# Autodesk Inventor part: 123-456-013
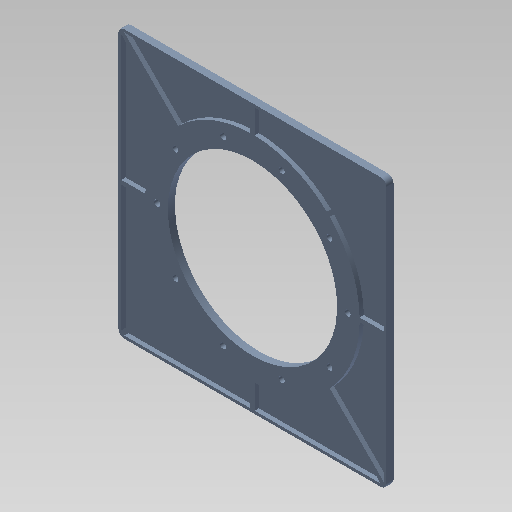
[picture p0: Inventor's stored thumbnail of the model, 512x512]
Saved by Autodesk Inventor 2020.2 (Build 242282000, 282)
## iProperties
Created: 2006-08
Part Number: 123-456-013
Document SubType Name: Modeling
Designer: F.Stasiak
Material: Staliwo
Description: Płyta
Density: 7.85 g/cm^3
Appearance: Stalowoniebieska - jasna
Mass: 74990.7 g
Surface Area: 15199.3 cm^2
Volume: 9552.95 cm^3
Manager: www.cadconsulting.pl
Company: Fabian Stasiak CAD Consulting
KODMAT: 14-2590
Author: F.Stasiak
Subject: Zbiór ćwiczeń. Autodesk Inventor 2020. Kurs podstawowy
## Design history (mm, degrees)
sketch "Szkic1"
  geometry: L1 (0, 475)-(950, 475); L2 (950, 475)-(950, -475); L3 (950, -475)-(0, -475); L4 (0, -475)-(0, 475); L5 (0, 0)-(950, 0); C1 r 300 at (475, 0); 1 further point
  constraints: 10 end point, 3 midpoint, 2 parallel, 1 centre point, 1 coincident, 1 horizontal, 1 perpendicular
  dimensions: "d0" = 950 distance of L3.end L1.start; "d1" = 950 distance of L2.end L3.end; "d2" = 600 diameter of C1
extrude "Wyciągnięcie proste1" new body sketch "Szkic1" distance "d3" = 25; taper "d4" = 0 deg
fillet "Zaokrąglenie1" dims "d8" = 20
feature "Skorupa1" dims "d9" = 80, "d10" = 10
sketch "Szkic2"
  geometry: L1 (455, -465)-(-455, -465) reference; L2 (465, 455)-(465, -455) reference; L3 (-455, 465)-(455, 465) reference; L4 (-465, -455)-(-465, 455) reference; L5 (-455, 455)-(455, -455); L6 (-455, -455)-(455, 455); L7 (-465, 0)-(465, 0); L8 (0, -465)-(0, 465); C1 r 380 at (0, 0) reference; C2 r 380 at (0, 0) reference; A1 r 10 centre (-455, -455) between (-465, -455) and (-455, -465) reference; A2 r 10 centre (455, -455) between (455, -465) and (465, -455) reference; A3 r 10 centre (455, 455) between (465, 455) and (455, 465) reference; A4 r 10 centre (-455, 455) between (-455, 465) and (-465, 455) reference
  constraints: 8 end point, 4 midpoint, 1 perpendicular
feature "Żebro1" sketch "Szkic2" dims "d11" = 15, "d12" = 1, "d13" = 0
sketch "Szkic3"
  geometry: 10 further points
hole "Otwór1" sketch "Szkic3" at (812.5, 0), (748.043, 198.378), (579.293, 320.982), (370.707, 320.982), (201.957, 198.378), (137.5, 0), (201.957, -198.378), (370.707, -320.982), (579.293, -320.982), (748.043, -198.378) diameter "d14" = 21; stored, may be unused: countersink angle "d18" = 90 deg, drill point angle "d20" = 120 deg; dims "d15" = 40, "d16" = 4, "d17" = 2, "d19" = 50
node "Bryła1"
node "Korpusy bryłowe"
node "Korpusy powierzchniowe"
node "Pętla rzutowana1"
feature "쀀䁆"
feature "쀀쁆"
